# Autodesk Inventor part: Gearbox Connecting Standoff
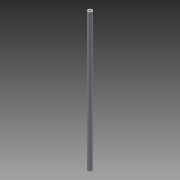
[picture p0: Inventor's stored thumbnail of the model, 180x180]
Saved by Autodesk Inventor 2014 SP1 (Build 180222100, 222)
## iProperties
Created: 2014-10
Part Number: Gearbox Connecting Standoff
Material: Aluminum 6061
Document SubType Name: Modeling
Designer: Michael
Density: 2.71 g/cm^3
Appearance: Aluminum - Flat
Author: Michael
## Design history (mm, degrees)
sketch "Sketch1"
  geometry: C1 r 2.489 at (0, 0); C2 r 6.35 at (0, 0); 1 further point
  constraints: 2 centre point, 2 coincident
  dimensions: "d0" = 4.9784 diameter of C1; "d1" = 12.7 diameter of C2
extrude "Extrusion1" new body sketch "Sketch1" stored distance "d2" = 393.7; taper "d3" = 0 deg
body "Solid1"
